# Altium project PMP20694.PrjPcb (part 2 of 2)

## Sheet PMP20694_BlankSheet.SchDoc
size 431 x 279 mm; Date: Not shown in title block; ApprovedBy: Not shown in title block; CheckedBy: Not shown in title block; Author: Not shown in title block; CompanyName: Not shown in title block; Engineer: Not shown in title block; Organization: Not shown in title block; Address1: Not shown in title block; Address2: Not shown in title block; Address3: Not shown in title block; Address4: Not shown in title block; DocumentNumber: 2; Revision: Use project parameter SCH_Rev; SheetNumber: 2; SheetTotal: 2; PageSetup: Record=PageOptions¦CenterHorizontal=True¦CenterVertical=True¦PrintScale=1.00¦XCorrection=1.00¦YCorrection=1.00¦PrintKind=0¦BorderSize=5000000¦LeftOffset=0¦BottomOffset=0¦Orientation=2¦PaperLength=1000¦PaperWidth=1000¦Scale=100¦PaperSource=15¦PrintQuality=600¦MediaType=1¦DitherType=10¦PaperKind=Letter¦PrintScaleMode=1
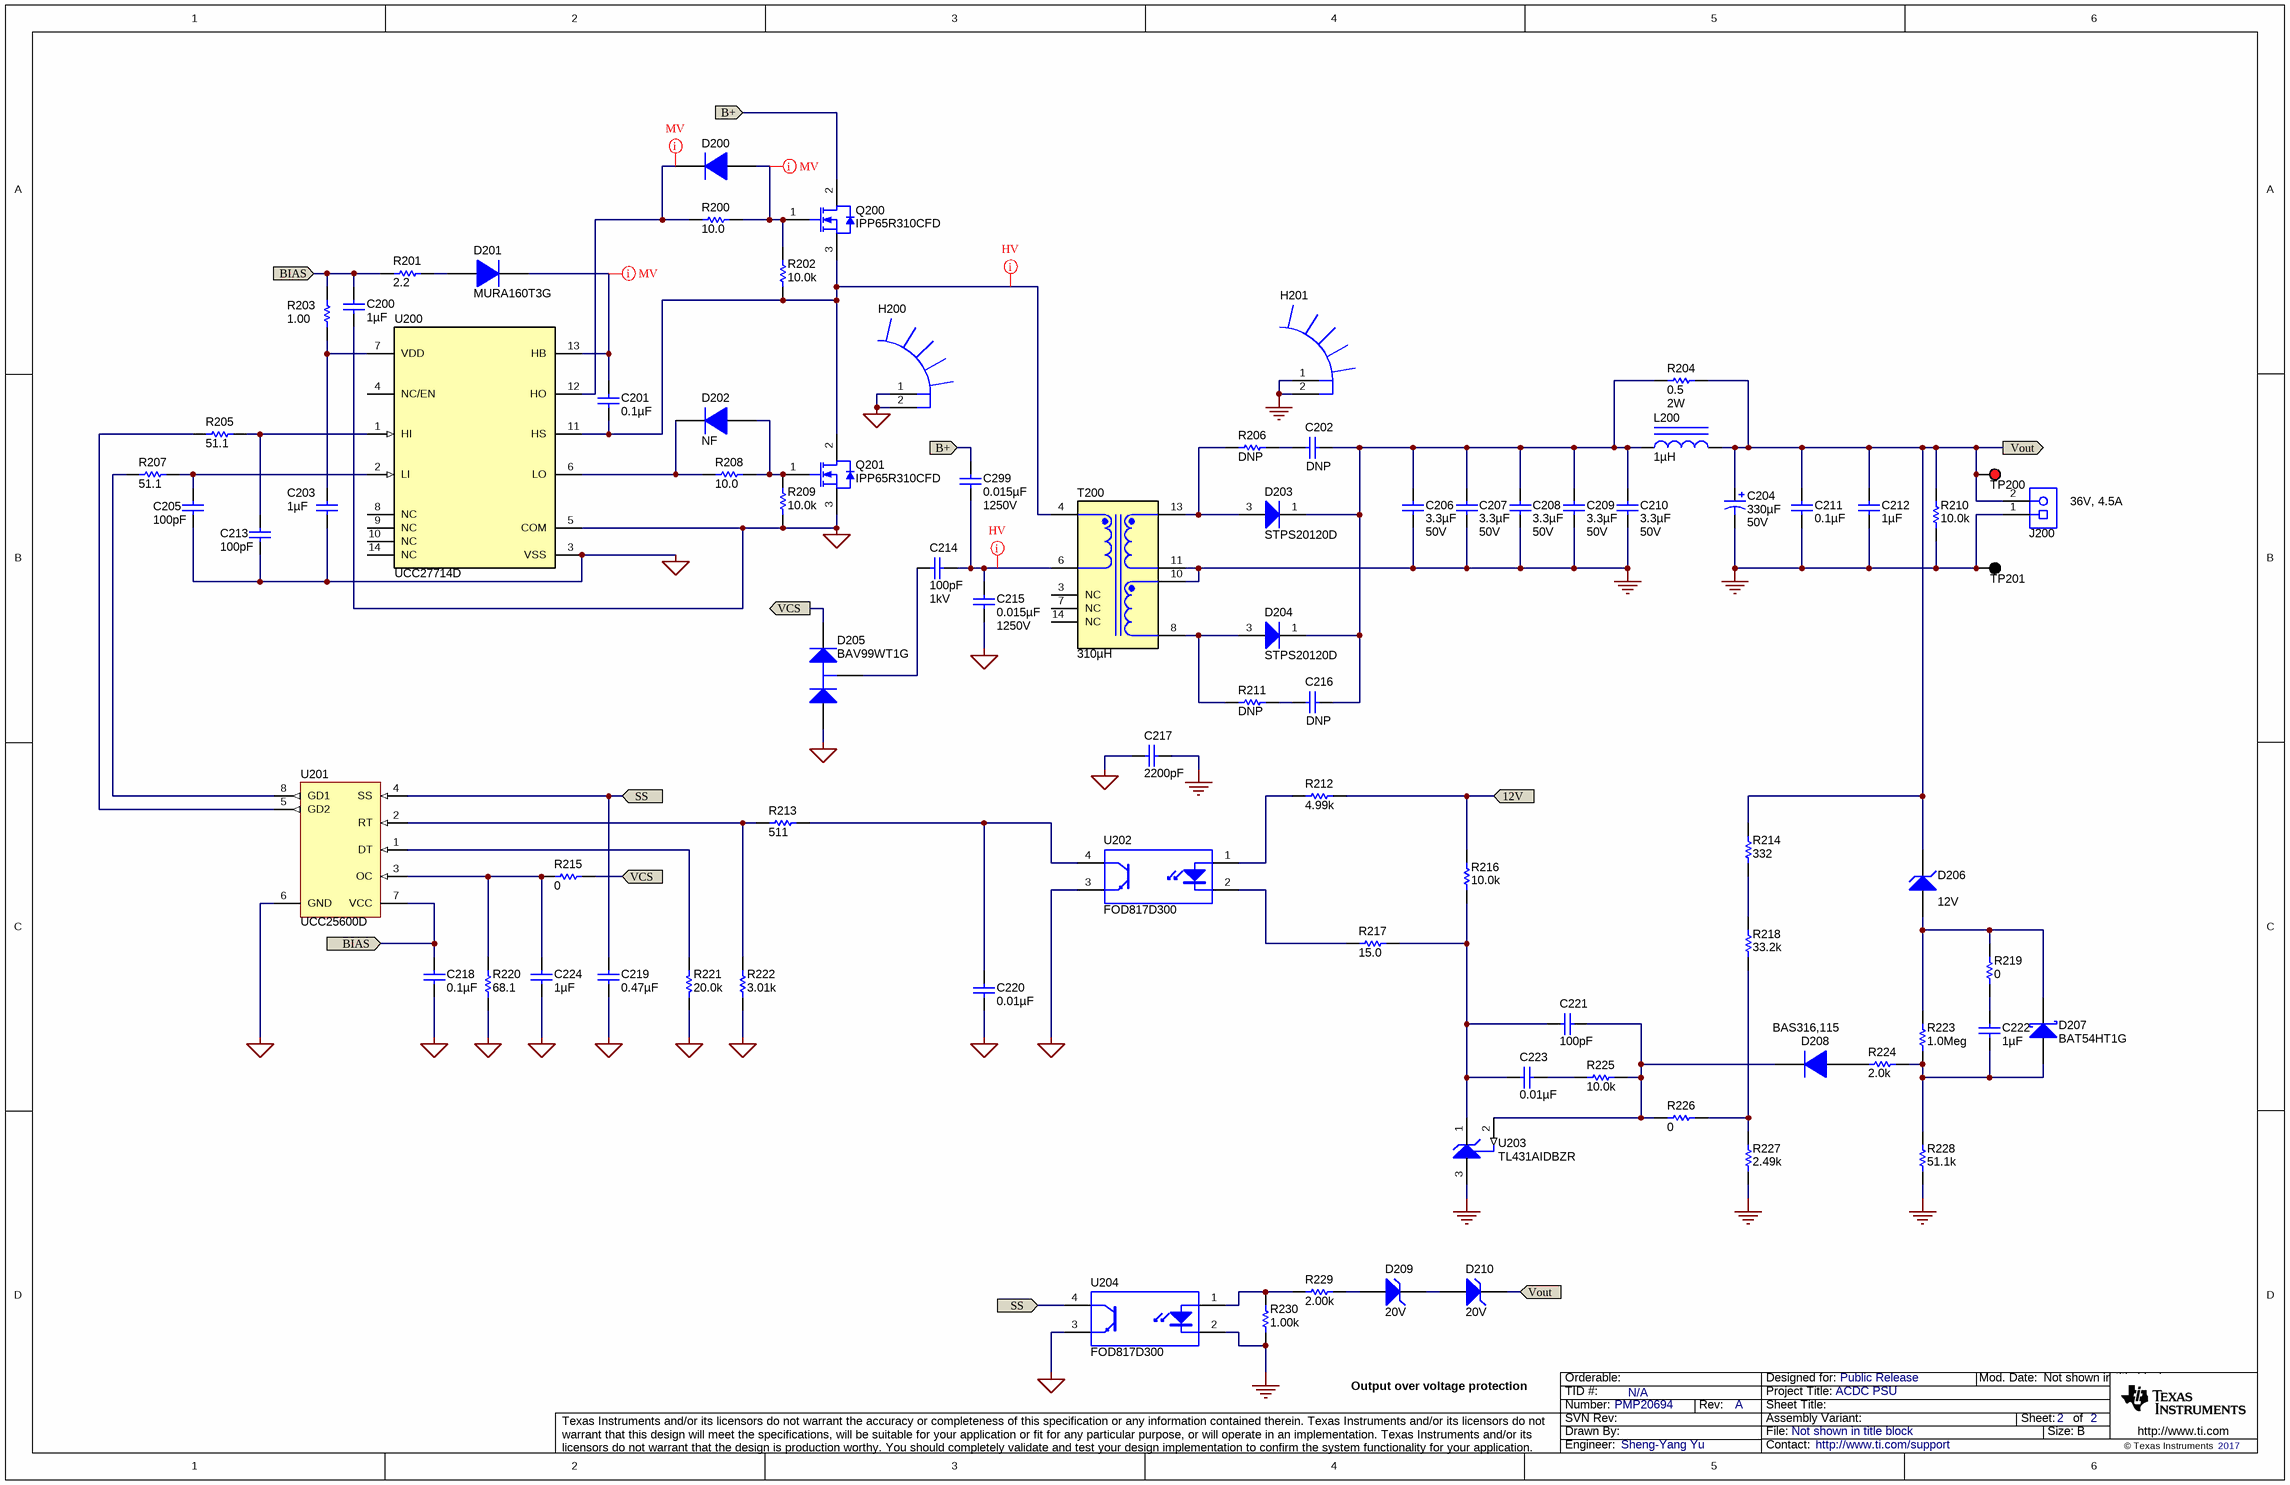
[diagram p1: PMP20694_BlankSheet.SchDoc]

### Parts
C200  ValueDisplayed: 1µF  [0603]  (hidden comment: UMK107AB7105KA-T)
C201  ValueDisplayed: 0.1µF  [1206]  (hidden comment: 12065C104KAT2A)
C202  value DNP  [1206]  (hidden comment: Used in BOM report)
C203  ValueDisplayed: 1µF  [1206]  (hidden comment: 12063C105KAT2A)
C204  ValueDisplayed: 330µF  Value2: 50V  [Chemi-Con_1000x2500]  (hidden comment: ELXZ500ELL331MJ25S)
C205  ValueDisplayed: 100pF  [0603]  (hidden comment: 06035A101FAT2A)
C206  ValueDisplayed: 3.3µF  Value2: 50V  [1210_280]  (hidden comment: C3225X5R1H335K250AB)
C207  ValueDisplayed: 3.3µF  Value2: 50V  [1210_280]  (hidden comment: C3225X5R1H335K250AB)
C208  ValueDisplayed: 3.3µF  Value2: 50V  [1210_280]  (hidden comment: C3225X5R1H335K250AB)
C209  ValueDisplayed: 3.3µF  Value2: 50V  [1210_280]  (hidden comment: C3225X5R1H335K250AB)
C210  ValueDisplayed: 3.3µF  Value2: 50V  [1210_280]  (hidden comment: C3225X5R1H335K250AB)
C211  ValueDisplayed: 0.1µF  [1206]  (hidden comment: 12065C104KAT2A)
C212  ValueDisplayed: 1µF  [1206_180]  (hidden comment: CGA5L3X7R1H105K160AB)
C213  ValueDisplayed: 100pF  [0603]  (hidden comment: 06035A101FAT2A)
C214  ValueDisplayed: 100pF  Value2: 1kV  [1808]  (hidden comment: 1206AC101KAT1A)
C215  ValueDisplayed: 0.015µF  Value2: 1250V  [CAPRR1500W80L1800T750H1300]  (hidden comment: 121MPE153J)
C216  value DNP  [1206]  (hidden comment: Used in BOM report)
C217  ValueDisplayed: 2200pF  [AY2_950x500_Straight]  (hidden comment: AY2222M35Y5US63L7)
C218  ValueDisplayed: 0.1µF  [0603]  (hidden comment: 06033C104JAT2A)
C219  ValueDisplayed: 0.47µF  [1206]  (hidden comment: 12063C474KAT2A)
C220  ValueDisplayed: 0.01µF  [0603]  (hidden comment: 06031C103JAT2A)
C221  ValueDisplayed: 100pF  [0603]  (hidden comment: 06033C101KAT2A)
C222  ValueDisplayed: 1µF  [0603]  (hidden comment: C0603C105K4PACTU)
C223  ValueDisplayed: 0.01µF  [0603]  (hidden comment: GRM188R61H103KA01D)
C224  ValueDisplayed: 1µF  [0603]  (hidden comment: C0603C105K4PACTU)
C299  ValueDisplayed: 0.015µF  Value2: 1250V  [CAPRR1500W80L1800T750H1300]  (hidden comment: 121MPE153J)
D200  NF  [sod-323]  (value not drawn)
D201  MURA160T3G  [SMA]
D202  NF  [sod-323]
D203  STPS20120D  [TO-220AC]
D204  STPS20120D  [TO-220AC]
D205  BAV99WT1G  [SOT-323]
D206  value 12V  [SOD-323]  (hidden comment: MMSZ5242BS-7-F)
D207  BAT54HT1G  [sod-323]
D208  BAS316,115  [sod-323]
D209  20V  [SOD-123]
D210  20V  [SOD-123]
H200  513102B02500G  [Aavid_513102B02500G]  (value not drawn)
H201  513102B02500G  [Aavid_513102B02500G]  (value not drawn)
J200  1715721  [PhoenixContact_1715721]  (value not drawn)
L200  ValueDisplayed: 1µH  [SRN6045TA]  (hidden comment: SRN6045TA-1R0Y)
Q200  IPP65R310CFD  [TO-220AB]
Q201  IPP65R310CFD  [TO-220AB]
R200  ValueDisplayed: 10.0  [0603]  (hidden comment: CRCW060310R0FKEA)
R201  ValueDisplayed: 2.2  [0805_HV]  (hidden comment: CRCW08052R20JNEA)
R202  value 10.0k  [0603]  (hidden comment: CRCW060310K0FKEA)
R203  value 1.00  [0805_HV]  (hidden comment: ERJ-6RQF1R0V)
R204  ValueDisplayed: 0.5  Value2: 2W  [2512]  (hidden comment: CSR2512FGR500)
R205  ValueDisplayed: 51.1  [0603]  (hidden comment: CRCW060351R1FKEA)
R206  value DNP  [2010]  (hidden comment: Used in BOM report)
R207  ValueDisplayed: 51.1  [0603]  (hidden comment: CRCW060351R1FKEA)
R208  ValueDisplayed: 10.0  [0603]  (hidden comment: CRCW060310R0FKEA)
R209  value 10.0k  [0603]  (hidden comment: CRCW060310K0FKEA)
R210  ValueDisplayed: 10.0k  [1206]  (hidden comment: CRCW120610K0FKEA)
R211  value DNP  [2010]  (hidden comment: Used in BOM report)
R212  value 4.99k  [1206]  (hidden comment: CRCW12064K99FKEA)
R213  ValueDisplayed: 511  [0603]  (hidden comment: CRCW0603511RFKEA)
R214  ValueDisplayed: 332  [0603]  (hidden comment: CRCW0603332RFKEA)
R215  value 0  [0603]  (hidden comment: CRCW06030000Z0EA)
R216  value 10.0k  [1206]  (hidden comment: CRCW120610K0FKEA)
R217  value 15.0  [0603]  (hidden comment: CRCW060315R0FKEA)
R218  ValueDisplayed: 33.2k  [0603]  (hidden comment: CRCW060333K2FKEA)
R219  value 0  [0603]  (hidden comment: CRCW06030000Z0EA)
R220  ValueDisplayed: 68.1  [0603]  (hidden comment: CRCW060368R1FKEA)
R221  value 20.0k  [0603]  (hidden comment: CRCW060320K0FKEA)
R222  ValueDisplayed: 3.01k  [0603]  (hidden comment: CRCW06033K01FKEA)
R223  value 1.0Meg  [0603]  (hidden comment: CRCW06031M00JNEA)
R224  value 2.0k  [0603]  (hidden comment: CRCW06032K00JNEA)
R225  value 10.0k  [0603]  (hidden comment: CRCW060310K0FKEA)
R226  value 0  [0603]  (hidden comment: CRCW06030000Z0EA)
R227  value 2.49k  [0603]  (hidden comment: CRCW06032K49FKEA)
R228  value 51.1k  [0603]  (hidden comment: CRCW060351K1FKEA)
R229  value 2.00k  [0603]  (hidden comment: RC0603FR-072KL)
R230  value 1.00k  [0603]  (hidden comment: CRCW06031K00FKEA)
T200  ValueDisplayed: 310µH  [Wurth_ERL35_5783_D125912]  (hidden comment: 750316706)
TP200  5000  [Keystone5000]  (value not drawn)
TP201  5001  [Keystone5001]  (value not drawn)
U200  UCC27714D  [D0014A_N]
U201  UCC25600D  [D0008A_N]
U202  FOD817D300  [DIP-4]
U203  TL431AIDBZR  [DBZ0003A_N]
U204  FOD817D300  [DIP-4]

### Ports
12V (in), B+ (in), BIAS (in), SS (in), VCS (in), VCS (out), Vout (in), Vout (out)

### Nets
PGND: C200.1 C203.2 C205.2 C213.1 C215.1 C217.2 C218.2 C219.2 C220.2 C224.2 D205.1(A) H200.1 H200.2 Q201.3(S) R209.2 R220.1 R221.1 R222.1 U200.3(VSS) U200.5(COM) U201.6(GND) U202.3(E) U204.3(E)
SGND: C204.2(-) C206.1 C207.1 C208.1 C209.1 C210.1 C211.2 C212.2 C217.1 H201.1 H201.2 J200.1 R210.1 R227.1 R228.1 R230.1 T200.10 T200.11 TP201.1 U203.3(ANODE) U204.2(K)
12V: R212.2 R216.2 ; port 12V
B+: C299.2 Q200.2(D) ; port B+
BIAS: C200.2 C218.1 R201.1 R203.2 U201.7(VCC) ; port BIAS
SS: C219.1 U201.4(SS) U204.4(C) ; port SS
VCS: D205.2(K) R215.2 ; port VCS
Vout: C204.1(+) C211.1 C212.1 D206.1(K) D210.1(K) J200.2 L200.2 R204.2 R210.2 R214.2 TP200.1 ; port Vout
NetC201_1: C201.1 D201.1(K) U200.13(HB)
NetC201_2: C201.2 Q200.3(S) Q201.2(D) R202.1 T200.4 U200.11(HS)
NetC202_1: C202.1 C206.2 C207.2 C208.2 C209.2 C210.2 C216.1 D203.1(K) D204.1(K) L200.1 R204.1
NetC202_2: C202.2 R206.1
NetC203_1: C203.1 R203.1 U200.7(VDD)
NetC205_1: C205.1 R207.1 U200.2(LI)
NetC213_2: C213.2 R205.1 U200.1(HI)
NetC214_1: C214.1 C215.2 C299.1 T200.6
NetC214_2: C214.2 D205.3(C)
NetC216_2: C216.2 R211.1
NetC220_1: C220.1 R213.2 U202.4(C)
NetC221_1: C221.1 D208.1(K) R225.2 R226.1 U203.2(REF)
NetC221_2: C221.2 C223.2 R216.1 R217.2 U203.1(CATHODE)
NetC222_1: C222.1 R219.1
NetC222_2: C222.2 D207.2(A) R223.1 R224.2 R228.2
NetC223_1: C223.1 R225.1
NetC224_1: C224.1 R215.1 R220.2 U201.3(OC)
NetD200_1: D200.1(K) R200.1 U200.12(HO)
NetD200_2: D200.2(A) Q200.1(G) R200.2 R202.2
NetD201_2: D201.2(A) R201.2
NetD202_1: D202.1(K) R208.1 U200.6(LO)
NetD202_2: D202.2(A) Q201.1(G) R208.2 R209.1
NetD203_3: D203.3(A) R206.2 T200.13
NetD204_3: D204.3(A) R211.2 T200.8
NetD206_2: D206.2(A) D207.1(K) R219.2 R223.2
NetD208_2: D208.2(A) R224.1
NetD209_1: D209.1(K) D210.2(A)
NetD209_2: D209.2(A) R229.2
NetR205_2: R205.2 U201.5(GD2)
NetR207_2: R207.2 U201.8(GD1)
NetR212_1: R212.1 U202.1(A)
NetR213_1: R213.1 R222.2 U201.2(RT)
NetR214_1: R214.1 R218.2
NetR217_1: R217.1 U202.2(K)
NetR218_1: R218.1 R226.2 R227.2
NetR221_2: R221.2 U201.1(DT)
NetR229_1: R229.1 R230.2 U204.1(A)

Not connected (* = marked no-connect by the designer): T200 3(NC) 7(NC) 14(NC); U200 4(NC/EN) 8(NC) 9(NC) 10(NC) 14(NC)

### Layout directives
net class HV: NetC201_2, NetC214_1
net class MV: NetC201_1, NetD200_1, NetD200_2

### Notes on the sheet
- (near J200) 36V, 4.5A
- Output over voltage protection

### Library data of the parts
C200 = UMK107AB7105KA-T: CAP, CERM, 1 µF, 50 V, +/- 10%, X7R, 0603; Manufacturer: Taiyo Yuden; Polarized: N; CompType: Capacitor; Value: 1uF; U/M: EA; Cap_F: 0.000001; Tolerance_%: 10; Value1: Unknown; VDC_V: 50; Value2: 50V; TaMin_C: -55; TaMax_C: 125
C201 C211 = 12065C104KAT2A: CAP, CERM, 0.1 µF, 50 V, +/- 10%, X7R, 1206; Manufacturer: AVX; Polarized: N; CompType: Capacitor; Value: 0.1uF; U/M: EA; Cap_F: 0.0000001; Tolerance_%: 10; ESR_ohm: 0.037; Value1: 0.037 ohm; VDC_V: 50; Value2: 50V; TaMin_C: -55; TaMax_C: 125; SizeArea_mm2: 5.12; SizeAreaWB_mm2: 10.92; SizeX_mm: 3.2; SizeY_mm: 1.6; SizeZ_mm: 1.35; AEC Category: Q200
C202 C216 = Capacitor: CAP, CERM, xxxF, xxV, [TempCo], xx%, [PackageReference]; Polarized: N; U/M: EA
C203 = 12063C105KAT2A: CAP, CERM, 1 µF, 25 V, +/- 10%, X7R, 1206; Manufacturer: AVX; Polarized: N; CompType: Capacitor; Value: 1uF; U/M: EA; Cap_F: 0.000001; Tolerance_%: 10; ESR_ohm: 0.013; Value1: 0.013 ohm; VDC_V: 25; Value2: 25V; TaMin_C: -55; TaMax_C: 125
C204 = ELXZ500ELL331MJ25S: CAP, AL, 330 µF, 50 V, +/- 20%, AEC-Q200 Grade 2, TH; Manufacturer: Chemi-Con; Polarized: Y; CompType: Capacitor; Value: 330uF; U/M: EA; Cap_F: 0.00033; Tolerance_%: 20; Value1: Unknown; VDC_V: 50; IRMS_A: 1.25; TaMin_C: -55; TaMax_C: 105; Cap_Case: 10x25mm; SizeAreaWB_mm2: 144; SizeArea_mm2: 100; SizeX_mm: 10; SizeZ_mm: 26.5; AEC Category: Q200; AEC Grade: 2
C205 C213 = 06035A101FAT2A: CAP, CERM, 100pF, 50V, +/-1%, C0G/NP0, 0603; Manufacturer: AVX; CompType: Capacitor; Tolerance_%: 1; Value1: Unknown; VDC_V: 50; U/M: EA; Polarized: N; Cap_F: 0.0000000001; TaMin_C: -55; TaMax_C: 125
C206-C210 = C3225X5R1H335K250AB: CAP, CERM, 3.3 µF, 50 V, +/- 10%, X5R, 1210; Manufacturer: TDK; Polarized: N; CompType: Capacitor; Value: 3.3uF; U/M: EA; Cap_F: 0.0000033; Tolerance_%: 10; ESR_ohm: 0.003158; Value1: 0.003158 ohm; VDC_V: 50; IRMS_A: 4.13891; TaMin_C: -55; TaMax_C: 85; SizeArea_mm2: 8; SizeAreaWB_mm2: 14.7; SizeX_mm: 3.2; SizeY_mm: 2.5; SizeZ_mm: 2.8; AEC Category: Q200
C212 = CGA5L3X7R1H105K160AB: CAP, CERM, 1 µF, 50 V, +/- 10%, X7R, AEC-Q200 Grade 1, 1206; Manufacturer: TDK; Polarized: N; CompType: Capacitor; Value: 1uF; U/M: EA; Cap_F: 0.000001; Tolerance_%: 10; ESR_ohm: 0.009289; Value1: 0.009289 ohm; VDC_V: 50; Value2: 50V; IRMS_A: 2.38446; TaMin_C: -55; TaMax_C: 125; SizeArea_mm2: 5.12; SizeAreaWB_mm2: 10.92; SizeX_mm: 3.2; SizeY_mm: 1.6; SizeZ_mm: 1.8; AEC Category: Q200; AEC Qualified: Y; AEC Grade: 1
C214 = VJ1808Y101KXEAT5Z: CAP CER 100PF 1KV X7R 1206; Manufacturer: AVX Corporation; Polarized: N; CompType: Capacitor; U/M: EA; Cap_F: 0.0000000001; Tolerance_%: 10; Value1: Unknown; VDC_V: 1000; TaMin_C: -55; TaMax_C: 125
C215 C299 = 121MPE153J: CAP, Film, 0.015 µF, 1250 V, +/- 5%, TH; Manufacturer: Rubycon; Polarized: N; CompType: Capacitor; Value: 0.015uF; U/M: EA; Cap_F: 0.000000015; Tolerance_%: 5; Value1: Unknown; VDC_V: 1250; TaMin_C: -40; TaMax_C: 105; Cap_Case: 18x7.5x13mm; AEC Category: Q200
C217 = AY2222M35Y5US63L7: CAP, CERM, 2200 pF, 300 V, +/- 20%, Y5U, AEC-Q200 Grade 1, D9.5xT5mm; Manufacturer: Vishay-Bccomponents; Polarized: N; CompType: Capacitor; Value: 2200pF; U/M: EA; Cap_F: 0.0000000022; Tolerance_%: 20; Value1: Unknown; VDC_V: 300; Value2: 300V; TaMin_C: -55; TaMax_C: 125; Cap_Case: 9.5x5mm; SizeArea_mm2: 47.5; SizeAreaWB_mm2: 80.5; SizeX_mm: 9.5; SizeY_mm: 5; SizeZ_mm: 14.5; AEC Category: Q200; AEC Qualified: Y; AEC Grade: 1
C218 = 06033C104JAT2A: CAP, CERM, 0.1uF, 25V, +/-5%, X7R, 0603; Manufacturer: AVX; Polarized: N; CompType: Capacitor; U/M: EA; Cap_F: 0.0000001; Tolerance_%: 5; ESR_Ohm: 0.05; Value1: 0.05 ohm; VDC_V: 25; TaMin_C: -55; TaMax_C: 125
C219 = 12063C474KAT2A: CAP, CERM, 0.47uF, 25V, +/-10%, X7R, 1206; Manufacturer: AVX; Polarized: N; CompType: Capacitor; U/M: EA; Cap_F: 0.00000047; Tolerance_%: 10; ESR_Ohm: 0.018; Value1: 0.018 ohm; VDC_V: 25; TaMin_C: -55; TaMax_C: 125
C220 = 06031C103JAT2A: CAP, CERM, 0.01 µF, 100 V, +/- 5%, X7R, 0603; Manufacturer: AVX; Polarized: N; CompType: Capacitor; Value: 0.01uF; U/M: EA; Cap_F: 0.00000001; Tolerance_%: 5; ESR_ohm: 0.098; Value1: 0.098 ohm; VDC_V: 100; Value2: 100V; TaMin_C: -55; TaMax_C: 125; SizeArea_mm2: 1.28; SizeAreaWB_mm2: 4.68; SizeX_mm: 1.6; SizeY_mm: 0.8; SizeZ_mm: 1; AEC Category: Q200
C221 = 06033C101KAT2A: CAP, CERM, 100pF, 25V, +/-10%, X7R, 0603; Manufacturer: AVX; Polarized: N; CompType: Capacitor; U/M: EA; Cap_F: 0.0000000001; Tolerance_%: 10; Value1: Unknown; VDC_V: 25; TaMin_C: -55; TaMax_C: 125
C222 C224 = C0603C105K4PACTU: CAP, CERM, 1uF, 16V, +/-10%, X5R, 0603; Manufacturer: Kemet; Polarized: N; CompType: Capacitor; U/M: EA; Cap_F: 0.000001; Tolerance_%: 10; Value1: Unknown; VDC_V: 16; TaMin_C: -55; TaMax_C: 85
C223 = GRM188R61H103KA01D: CAP, CERM, 0.01 µF, 50 V, +/- 10%, X5R, 0603; Manufacturer: MuRata; Polarized: N; CompType: Capacitor; Value: 0.01uF; U/M: EA; Cap_F: 0.00000001; Tolerance_%: 10; Value1: Unknown; VDC_V: 50; Value2: 50V; TaMin_C: -55; TaMax_C: 85; SizeArea_mm2: 1.28; SizeAreaWB_mm2: 4.68; SizeX_mm: 1.6; SizeY_mm: 0.8; SizeZ_mm: 1; AEC Category: Q200
D200 D202 = BAS316,115: Diode, Ultrafast, 100V, 0.25A, SOD-323; Manufacturer: NXP Semiconductor; U/M: EA; Vf_V: 1.4; Value2: 1.4V; Io_A: 0.25; Vr_V: 100; TJmax_C: 150
D201 = MURA160T3G: Diode, Ultrafast, 600 V, 1 A, SMA; Manufacturer: ON Semiconductor; U/M: EA; Vf_V: 1.05; Value: 600V; Value1: 1A; Value2: 1.05V; Io_A: 1; Vr_V: 600; TJmax_C: 175; AEC Category: Q101
D203 D204 = MBR10100G: DIODE SCHOTTKY 120V 20A TO220AB; Manufacturer: STMicroelectronics; SymbolCreator: a0412235; U/M: EA; Vf_V: 0.8; Value2: 0.8V; Io_A: 10; Vr_V: 120; TJmax_C: 175; RJC_CperW: 2; SizeAreaWB_mm2: 78.975; SizeArea_mm2: 45.675; SizeX_mm: 10.15; SizeY_mm: 4.5; SizeZ_mm: 23; AEC Category: Q101
D205 = BAV99WT1G: Diode, P-N, 70V, 0.2A, SOT-323; Manufacturer: Fairchild Semiconductor; Value: 0.63V; U/M: EA; Vf_V: 0.63; Io_A: 0.2; Vr_V: 70; TJmax_C: 150
D206 = MMSZ5242BS-7-F: Diode, Zener, 12 V, 200 mW, SOD-323; Manufacturer: Diodes Inc.; SymbolCreator: a0412235; U/M: EA; Power_W: 0.2; Vz_V: 12; Value1: 0.2W; RJA_CperW: 350; SizeAreaWB_mm2: 8.695; SizeArea_mm2: 3.645; SizeX_mm: 2.7; SizeY_mm: 1.35; SizeZ_mm: 1; AEC Category: Q101
D207 = BAT54HT1G: Diode, Schottky, 30V, 0.2A, SOD-323; Manufacturer: ON Semiconductor; Value: 0.35V; U/M: EA; Vf_V: 0.35; Io_A: 0.2; Vr_V: 30
D208 = BAS316,115: Diode, Ultrafast, 100V, 0.25A, SOD-323; Manufacturer: NXP Semiconductor; Value: 1.4V; U/M: EA; Vf_V: 1.4; Io_A: 0.25; Vr_V: 100; TJmax_C: 150
D209 D210 = MMSZ5250B-7-F: Diode, Zener, 20V, 500mW, SOD-123; Manufacturer: Diodes Inc.; U/M: EA; Power_W: 0.5; Vz_V: 20; Value1: 0.5W; RJA_CperW: 350
H200 H201 = 513102B02500G: Extruded heat sink with radial fins; Manufacturer: Aavid; SymbolCreator: a0799628
J200 = 1715721: Terminal Block, 5.08 mm, 2x1, TH; Manufacturer: Phoenix Contact; SymbolCreator: a0412235; Pitch_mm: 5.08; Gender: Female; Row_Count: 1; ContactFinish: Tin; Current_A: 17.5; Voltage_V: 400; Cert_CSA: Y; Cert_CULUS: N
L200 = SRN6045TA-1R0Y: Inductor, Shielded, Ferrite, 1 µH, 8 A, 0.012 ohm, AEC-Q200 Grade 1, SMD; Manufacturer: Bourns; Value: 1uH; Ind_H: 1.0E-6; Imax_A: 8; Irms: 8A @ 40C rise; Isat: 13.5A @ 30% inductance drop; DCR_ohm: 0.012; Value2: 8A; SizeAreaWB_mm2: 64; SizeArea_mm2: 36; SizeX_mm: 6; SizeZ_mm: 4.5; AEC Category: Q200; AEC Qualified: Y; AEC Grade: 1
Q200 Q201 = IPP65R190CFD: MOSFET N-CH 650V 11.4A TO220; Manufacturer: Infineon Technologies; Alternate Manufacturer: None; U/M: EA; ChType: N; Value1: 0.19 ohm; Rdson45_ohm: 0.19; QgTyp_nC: 68; IdsMax_A: 17.5; SizeAreaWB_mm2: 79.3; SizeArea_mm2: 45.9; SizeX_mm: 10.2; SizeY_mm: 4.5; SizeZ_mm: 19.4; AEC Category: Q101
R200 R208 = CRCW060310R0FKEA: RES, 10.0, 1%, 0.1 W, 0603; Manufacturer: Vishay-Dale; CompType: Resistor; Value: 10.0; Res_ohm: 10; Value_Code: 10R0; Tolerance_%: 1; Power_W: 0.1; Value2: 0.1W; VDC_V: 75; TempCo: 100 ppm/C; SizeArea_mm2: 1.28; SizeX_mm: 1.6; SizeY_mm: 0.8; EIA_Code: E96; U/M: EA; AEC Category: Q200
R201 = CRCW08052R20JNEA: RES, 2.2, 5%, 0.125 W, 0805; Manufacturer: Vishay-Dale; CompType: Resistor; Value: 2.2; Value_Code: 2R20; Tolerance_%: 5; Power_W: 0.125; Value2: 0.125W; VDC_V: 150; TempCo: 200 ppm/C; EIA_Code: E24; U/M: EA
R202 R209 R225 = CRCW060310K0FKEA: RES, 10.0k ohm, 1%, 0.1W, 0603; Manufacturer: Vishay-Dale; CompType: Resistor; Res_ohm: 10000; Value_Code: 10k0; Tolerance_%: 1; Power_W: 0.1; VDC_V: 75; TempCo: 100 ppm/C; EIA_Code: E96; U/M: EA
R203 = ERJ-6RQF1R0V: RES, 1.00 ohm, 1%, 0.125W, 0805; Manufacturer: Panasonic; CompType: Resistor; Res_ohm: 1; Value_Code: 1R00; Power_W: 0.125; TempCo: 200 ppm/C; EIA_Code: E96; U/M: EA
R204 = CSR2512FGR500: RES, 0.5, 1%, 2 W, 2512; Manufacturer: Stackpole Electronics Inc; CompType: Resistor; Value: 0.5; Value_Code: R500; Tolerance_%: 1; Power_W: 2; TempCo: 200 ppm/C; SizeArea_mm2: 20.16; SizeX_mm: 6.3; SizeY_mm: 3.2; SizeZ_mm: 0.71; U/M: EA; AEC Category: Q200
R205 R207 = CRCW060351R1FKEA: RES, 51.1, 1%, 0.1 W, 0603; Manufacturer: Vishay-Dale; CompType: Resistor; Value: 51.1; Value_Code: 51R1; Tolerance_%: 1; Power_W: 0.1; Value2: 0.1W; VDC_V: 75; TempCo: 100 ppm/C; EIA_Code: E96; U/M: EA
R206 R211 = Resistor: RES, xxx ohm, x%, xW, [PackageReference]; U/M: EA
R210 = CRCW120610K0FKEA: RES, 10.0 k, 1%, 0.25 W, 1206; Manufacturer: Vishay-Dale; CompType: Resistor; Value: 10.0k; Res_ohm: 10000; Value_Code: 10k0; Tolerance_%: 1; Power_W: 0.25; Value2: 0.25W; VDC_V: 200; TempCo: 100 ppm/C; SizeArea_mm2: 5.12; SizeX_mm: 3.2; SizeY_mm: 1.6; SizeZ_mm: 1.35; EIA_Code: E96; U/M: EA; AEC Category: Q200
R212 = CRCW12064K99FKEA: RES, 4.99k ohm, 1%, 0.25W, 1206; Manufacturer: Vishay-Dale; CompType: Resistor; Res_ohm: 4990; Value_Code: 4k99; Tolerance_%: 1; Power_W: 0.25; VDC_V: 200; TempCo: 100 ppm/C; EIA_Code: E96; U/M: EA
R213 = CRCW0603511RFKEA: RES, 511, 1%, 0.1 W, 0603; Manufacturer: Vishay-Dale; CompType: Resistor; Value: 511; Value_Code: 511R; Tolerance_%: 1; Power_W: 0.1; Value2: 0.1W; VDC_V: 75; TempCo: 100 ppm/C; SizeArea_mm2: 1.28; SizeX_mm: 1.6; SizeY_mm: 0.8; EIA_Code: E96; U/M: EA; AEC Category: Q200
R214 = CRCW0603332RFKEA: RES, 332, 1%, 0.1 W, 0603; Manufacturer: Vishay-Dale; CompType: Resistor; Value: 332; Value_Code: 332R; Tolerance_%: 1; Power_W: 0.1; Value2: 0.1W; VDC_V: 75; TempCo: 100 ppm/C; SizeArea_mm2: 1.28; SizeX_mm: 1.6; SizeY_mm: 0.8; EIA_Code: E96; U/M: EA; AEC Category: Q200
R215 R219 R226 = CRCW06030000Z0EA: RES, 0 ohm, 5%, 0.1W, 0603; Manufacturer: Vishay-Dale; CompType: Resistor; Value_Code: 0000; Tolerance_%: 5; Power_W: 0.1; VDC_V: 75; TempCo: 200 ppm/C; EIA_Code: E24; U/M: EA
R216 = CRCW120610K0FKEA: RES, 10.0k ohm, 1%, 0.25W, 1206; Manufacturer: Vishay-Dale; CompType: Resistor; Res_ohm: 10000; Value_Code: 10k0; Tolerance_%: 1; Power_W: 0.25; VDC_V: 200; TempCo: 100 ppm/C; EIA_Code: E96; U/M: EA
R217 = CRCW060315R0FKEA: RES, 15.0 ohm, 1%, 0.1W, 0603; Manufacturer: Vishay-Dale; CompType: Resistor; Res_ohm: 15; Value_Code: 15R0; Tolerance_%: 1; Power_W: 0.1; VDC_V: 75; TempCo: 100 ppm/C; EIA_Code: E96; U/M: EA
R218 = CRCW060333K2FKEA: RES, 33.2 k, 1%, 0.1 W, 0603; Manufacturer: Vishay-Dale; CompType: Resistor; Value: 33.2k; Res_ohm: 33200; Value_Code: 33k2; Tolerance_%: 1; Power_W: 0.1; Value2: 0.1W; VDC_V: 75; TempCo: 100 ppm/C; SizeArea_mm2: 1.28; SizeX_mm: 1.6; SizeY_mm: 0.8; EIA_Code: E96; U/M: EA; AEC Category: Q200
R220 = CRCW060368R1FKEA: RES, 68.1, 1%, 0.1 W, 0603; Manufacturer: Vishay-Dale; CompType: Resistor; Value: 68.1; Value_Code: 68R1; Tolerance_%: 1; Power_W: 0.1; Value2: 0.1W; VDC_V: 75; TempCo: 100 ppm/C; SizeArea_mm2: 1.28; SizeX_mm: 1.6; SizeY_mm: 0.8; EIA_Code: E96; U/M: EA; AEC Category: Q200
R221 = CRCW060320K0FKEA: RES, 20.0k ohm, 1%, 0.1W, 0603; Manufacturer: Vishay-Dale; CompType: Resistor; Res_ohm: 20000; Value_Code: 20k0; Tolerance_%: 1; Power_W: 0.1; VDC_V: 75; TempCo: 100 ppm/C; EIA_Code: E96; U/M: EA
R222 = CRCW06033K01FKEA: RES, 3.01 k, 1%, 0.1 W, 0603; Manufacturer: Vishay-Dale; CompType: Resistor; Value: 3.01k; Res_ohm: 3010; Value_Code: 3k01; Tolerance_%: 1; Power_W: 0.1; Value2: 0.1W; VDC_V: 75; TempCo: 100 ppm/C; SizeArea_mm2: 1.28; SizeX_mm: 1.6; SizeY_mm: 0.8; EIA_Code: E96; U/M: EA; AEC Category: Q200
R223 = CRCW06031M00JNEA: RES, 1.0Meg ohm, 5%, 0.1W, 0603; Manufacturer: Vishay-Dale; CompType: Resistor; Res_ohm: 1000000; Value_Code: 1M00; Tolerance_%: 5; Power_W: 0.1; VDC_V: 75; TempCo: 200 ppm/C; EIA_Code: E24; U/M: EA
R224 = CRCW06032K00JNEA: RES, 2.0k ohm, 5%, 0.1W, 0603; Manufacturer: Vishay-Dale; CompType: Resistor; Res_ohm: 2000; Value_Code: 2k00; Tolerance_%: 5; Power_W: 0.1; VDC_V: 75; TempCo: 200 ppm/C; EIA_Code: E24; U/M: EA
R227 = CRCW06032K49FKEA: RES, 2.49k ohm, 1%, 0.1W, 0603; Manufacturer: Vishay-Dale; CompType: Resistor; Res_ohm: 2490; Value_Code: 2k49; Tolerance_%: 1; Power_W: 0.1; VDC_V: 75; TempCo: 100 ppm/C; EIA_Code: E96; U/M: EA
R228 = CRCW060351K1FKEA: RES, 51.1k ohm, 1%, 0.1W, 0603; Manufacturer: Vishay-Dale; CompType: Resistor; Res_ohm: 51100; Value_Code: 51k1; Tolerance_%: 1; Power_W: 0.1; VDC_V: 75; TempCo: 100 ppm/C; EIA_Code: E96; U/M: EA
R229 = RC0603FR-072KL: RES, 2.00k ohm, 1%, 0.1W, 0603; Manufacturer: Yageo America; CompType: Resistor; Res_ohm: 2000; Value_Code: 2k00; Tolerance_%: 1; Power_W: 0.1; VDC_V: 150; TempCo: 200 ppm/C; EIA_Code: E96; U/M: EA
R230 = CRCW06031K00FKEA: RES, 1.00k ohm, 1%, 0.1W, 0603; Manufacturer: Vishay-Dale; CompType: Resistor; Res_ohm: 1000; Value_Code: 1k00; Tolerance_%: 1; Power_W: 0.1; VDC_V: 75; TempCo: 100 ppm/C; EIA_Code: E96; U/M: EA
T200 = 750316706: Transformer, 310 uH, ERL35, TH; Manufacturer: Wurth Elektronik; SymbolCreator: Altium; Value: 310uH; Lp: 310; DCR_ohm: 0.1; LeakageL: 70; Ns1toNp: 0.161; Rs1: 0.015; SizeAreaWB_mm2: 1771; SizeArea_mm2: 1606; SizeX_mm: 44; SizeY_mm: 36.5; SizeZ_mm: 28.5
TP200 = 5000: Test Point, Miniature, Red, TH; Manufacturer: Keystone; CompType: Test Point Loop; ContactFinish: Silver
TP201 = 5001: Test Point, Miniature, Black, TH; Manufacturer: Keystone; CompType: Test Point Loop; ContactFinish: Silver
U200 = UCC27714D: High-Speed, 4-A, 600-V High-Side Low-Side Gate Driver, D0014A (SOIC-14); Manufacturer: Texas Instruments; SymbolCreator: a0411947; SizeArea_mm2: 51.9; SizeAreaWB_mm2: 85.2; SizeX_mm: 6; SizeY_mm: 8.65; SizeZ_mm: 1.75; CompType: IC; U/M: EA
U201 = UCC25600D: High-Performance Resonant Mode Controller with Voltage Control, 50 % Duty Cycle, -40 to +125 degC, 8-pin SOIC (D), Green (RoHS & no Sb/Br); Manufacturer: Texas Instruments; Alternate Manufacturer: None; Alternate PartNumber: Equivalent; Duty Cycle(Max)(%): 50; Frequency(Max)(kHz): 350; Rating: Catalog; Regulated Outputs(#): 2; SubFamily: PWM Controller; Topology: Resonant, Half-Bridge; UVLO Thresholds On/Off(V): 10.5/9.5
U202 U204 = FOD817A: OPTOISOLATOR 5KV TRANSISTOR 4DIP; Manufacturer: Fairchild/ON Semiconductor; CTR (Min): 300%; CTR (Max): 600%; Voltage_Isolation_Vrms: 5000V; CompType: Optocoupler; SizeAreaWB_mm2: 71.064; SizeArea_mm2: 40.304; SizeX_mm: 8.8; SizeY_mm: 4.58; SizeZ_mm: 5
U203 = TL431AIDBZR: Adjustable Precision Shunt Regulator, 34 ppm / degC, 100 mA, -40 to 85 degC, 3-pin SOT-23 (DBZ), Green (RoHS & no Sb/Br); Manufacturer: Texas Instruments; Alternate PartNumber: Equivalent; Initial Accuracy @ 25/deg C(%): 1; Iout/Iz(Max)(mA): 100; Min Iz for Regulation(uA): 600; Rating: Catalog; SubFamily: Shunt Voltage Reference; Temp Coeff(Max)(ppm/ degree C): 92; Temp Coeff(Typ)(ppm/ degree C): 34; VO Adj(Max)(V): 36; VO Adj(Min)(V): 2.495

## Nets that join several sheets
PGND: PMP20694_CoverSheet (46 pins), PMP20694_BlankSheet (23 pins)
SGND: PMP20694_CoverSheet (6 pins), PMP20694_BlankSheet (21 pins)
12V: PMP20694_CoverSheet (6 pins), PMP20694_BlankSheet (R212.2 R216.2)
B+: PMP20694_CoverSheet (5 pins), PMP20694_BlankSheet (C299.2 Q200.2)
BIAS: PMP20694_CoverSheet (10 pins), PMP20694_BlankSheet (5 pins)
SS: PMP20694_CoverSheet (D111.1 U102.1), PMP20694_BlankSheet (C219.1 U201.4 U204.4)

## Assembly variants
001: not fitted C202 C216 R117 R206 R211 T100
